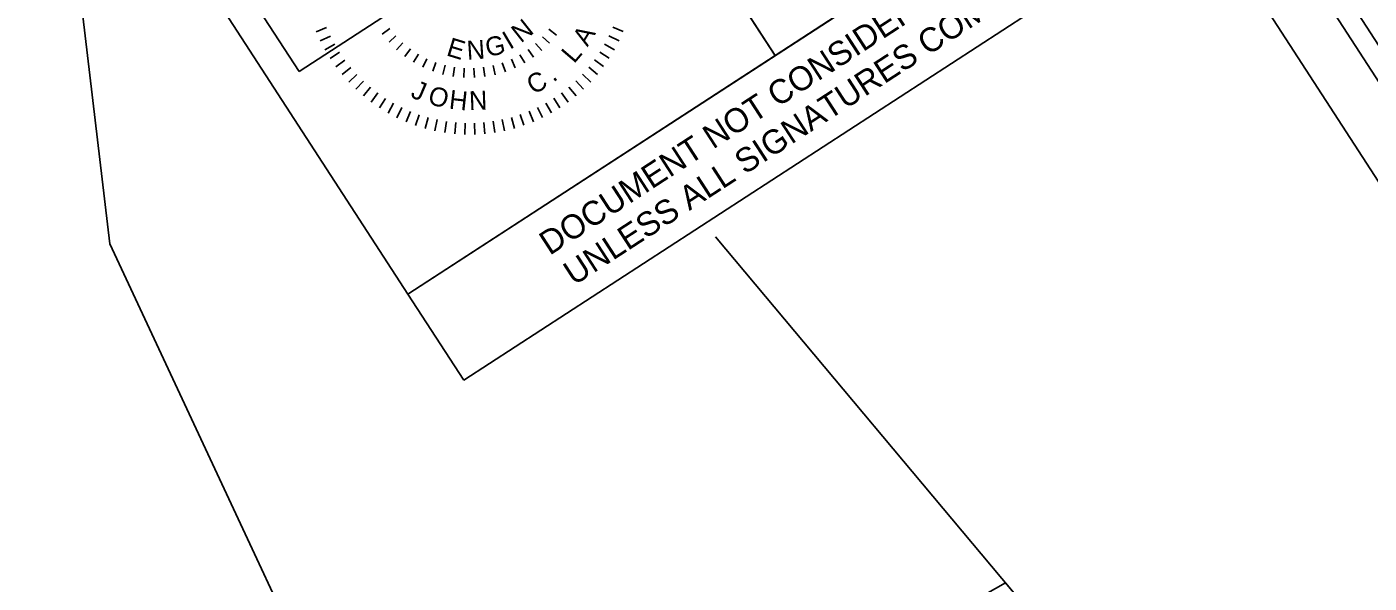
# Model space of a CAD drawing. Extents: x 555170 to 557181, y 503234 to 505074.
# Drawn here: x 556408.1 to 556715, y 504743 to 504870 of the extents above; entities that cross this region are included whole.
import ezdxf

# ---------------------------------------------------------------- set-up
doc = ezdxf.new("R2010")
doc.units = 0
for name, color, linetype in [('Matchline', 7, 'Continuous'), ('Old_Level_21', 7, 'Continuous'), ('Sheet Border Standard 30in CELL', 7, 'Continuous'), ('Sheet Clip Boundary CELL', 7, 'Continuous'), ('Sheet Plot Border Inside CELL', 7, 'Continuous'), ('Sheet Plot Border Outside CELL', 7, 'Continuous'), ('Sheet Sticker Exception Certification CELL', 7, 'Continuous'), ('Sheet Sticker Incomplete CELL', 7, 'Continuous')]:
    doc.layers.add(name, color=color, linetype=linetype)

msp = doc.modelspace()

# ---------------------------------------------------------------- linework, layer by layer
at = {"layer": 'Matchline'}
msp.add_line((556565.58, 504822.05), (556936.88, 504379.27), dxfattribs=at)
at = {"layer": 'Old_Level_21'}
for p, q in [((556474.26, 504868.87), (556476.65, 504869.86)), ((556475.2, 504866.78), (556477.53, 504867.91)), ((556489.37, 504868.33), (556491.09, 504869.63)), ((556490.93, 504866.48), (556492.51, 504867.94)), ((556527.6, 504866.28), (556526.02, 504867.76)), ((556529.17, 504868.12), (556527.46, 504869.44)), ((556543.52, 504866.82), (556541.19, 504867.95)), ((556544.46, 504868.91), (556542.07, 504869.9)), ((556476.27, 504864.75), (556478.52, 504866.02)), ((556477.46, 504862.78), (556479.63, 504864.19)), ((556492.65, 504864.77), (556494.09, 504866.38)), ((556494.53, 504863.25), (556495.8, 504864.99)), ((556523.96, 504863.09), (556522.7, 504864.84)), ((556525.85, 504864.6), (556524.43, 504866.22)), ((556541.27, 504862.82), (556539.1, 504864.23)), ((556542.46, 504864.78), (556540.2, 504866.06)), ((556478.77, 504860.89), (556480.85, 504862.43)), ((556496.54, 504861.92), (556497.64, 504863.77)), ((556498.67, 504860.78), (556499.6, 504862.73)), ((556500.91, 504859.85), (556501.64, 504861.88)), ((556503.23, 504859.15), (556503.76, 504861.24)), ((556505.6, 504858.67), (556505.92, 504860.81)), ((556512.84, 504858.63), (556512.54, 504860.77)), ((556515.22, 504859.08), (556514.71, 504861.19)), ((556516.82, 504861.8), (556517.52, 504859.76)), ((556519.78, 504860.66), (556518.88, 504862.62)), ((556521.93, 504861.78), (556520.84, 504863.64)), ((556538.56, 504859.12), (556536.56, 504860.78)), ((556539.97, 504860.93), (556537.88, 504862.46)), ((556480.18, 504859.09), (556482.17, 504860.74)), ((556481.7, 504857.37), (556483.59, 504859.14)), ((556508.01, 504858.43), (556508.12, 504860.58)), ((556510.43, 504858.41), (556510.33, 504860.57)), ((556537.03, 504857.4), (556535.15, 504859.18)), ((556483.33, 504855.75), (556485.1, 504857.63)), ((556485.05, 504854.22), (556486.71, 504856.22)), ((556486.85, 504852.81), (556488.39, 504854.9)), ((556531.89, 504852.84), (556530.36, 504854.93)), ((556533.69, 504854.26), (556532.04, 504856.25)), ((556535.41, 504855.78), (556533.64, 504857.66)), ((556488.75, 504851.51), (556490.15, 504853.68)), ((556490.71, 504850.32), (556491.98, 504852.58)), ((556492.74, 504849.26), (556493.87, 504851.59)), ((556526.01, 504849.28), (556524.87, 504851.61)), ((556528.04, 504850.35), (556526.76, 504852.6)), ((556530, 504851.54), (556528.59, 504853.71)), ((556494.84, 504848.32), (556495.82, 504850.71)), ((556496.98, 504847.51), (556497.82, 504849.95)), ((556499.17, 504846.82), (556499.87, 504849.32)), ((556501.4, 504846.28), (556501.94, 504848.81)), ((556517.35, 504846.29), (556516.81, 504848.82)), ((556519.58, 504846.83), (556518.88, 504849.33)), ((556521.77, 504847.52), (556520.92, 504849.97)), ((556523.92, 504848.34), (556522.92, 504850.73)), ((556503.66, 504845.86), (556504.05, 504848.42)), ((556505.94, 504845.59), (556506.17, 504848.17)), ((556508.23, 504845.45), (556508.31, 504848.04)), ((556510.52, 504845.45), (556510.45, 504848.04)), ((556512.82, 504845.59), (556512.58, 504848.17)), ((556515.09, 504845.87), (556514.7, 504848.43))]:
    msp.add_line(p, q, dxfattribs=at)
at = {"layer": 'Sheet Border Standard 30in CELL'}
msp.add_line((556517.88, 504957.83), (556579.13, 504863.53), dxfattribs=at)
for points in [[(556581.3, 505043.79), (555323.3, 504226.82), (555895.18, 503346.22), (557153.18, 504163.19)], [(556517.88, 504957.83), (556601.75, 505012.3), (556663.02, 504917.95), (556579.16, 504863.48)], [(556433.97, 504903.34), (556517.88, 504957.83), (556579.16, 504863.48), (556495.25, 504808.99)]]:
    msp.add_lwpolyline(points, close=True, dxfattribs=at)
at = {"layer": 'Sheet Clip Boundary CELL'}
msp.add_lwpolyline([(555838.52, 503433.47), (555757.63, 503602.94), (555641.38, 503854.94), (555665.07, 503867.43), (555636.39, 503915.75), (555617.07, 503908.99), (555456.45, 504257.61), (555437.06, 504299.18), (556413.52, 504934.83), (556427.07, 504820.42), (556498.53, 504667.56), (556631.84, 504743.04), (556936.88, 504379.27), (557153.18, 504163.19), (555896.02, 503346.77)], close=True, dxfattribs=at)
at = {"layer": 'Sheet Plot Border Inside CELL'}
msp.add_lwpolyline([(556590.39, 505052.74), (555192.76, 504145.08), (555767.42, 503260.21), (557165.05, 504167.86)], close=True, dxfattribs=at)
at = {"layer": 'Sheet Plot Border Outside CELL'}
msp.add_lwpolyline([(556581.94, 505074.02), (555169.63, 504156.83), (555768.74, 503234.3), (557181.05, 504151.49)], close=True, dxfattribs=at)
at = {"layer": 'Sheet Sticker Exception Certification CELL'}
for p, q in [((556495.25, 504808.99), (556663.01, 504917.94)), ((556675.81, 504898.23), (556508.05, 504789.28)), ((556508.05, 504789.28), (556495.25, 504808.99))]:
    msp.add_line(p, q, dxfattribs=at)
at = {"layer": 'Sheet Sticker Incomplete CELL'}
msp.add_lwpolyline([(556470.36, 504859.78), (556454.37, 504884.41), (556608.47, 504984.49), (556624.47, 504959.85)], close=True, dxfattribs=at)

# ---------------------------------------------------------------- texts
at = {"layer": 'Old_Level_21'}
for s, rotation, p in [('N', 38.3367, (556521.06, 504866.18)), ('E', 342.9909, (556503.82, 504863.53)), ('N', 3.846, (556508.82, 504862.48)), ('G', 12.6122, (556513.46, 504863.08)), ('I', 30.707, (556518.52, 504864.71)), ('A', 58.54, (556536.28, 504865.32)), ('L', 49.5374, (556533.22, 504861.46)), ('C', 29.0108, (556523.91, 504854.44)), ('.', 36.7531, (556528.47, 504857.25)), ('J', 336.8558, (556495.64, 504854.03)), ('O', 344.9277, (556499.57, 504852.49)), ('H', 353.5704, (556504.5, 504851.35)), ('N', 2.243, (556509.29, 504850.98))]:
    msp.add_text(s, height=4.31, rotation=rotation, dxfattribs=at).set_placement(p)
at = {"layer": 'Sheet Sticker Exception Certification CELL'}
for s, p in [('DOCUMENT NOT CONSIDERED FINAL', (556527.64, 504817.69)), ('UNLESS ALL SIGNATURES COMPLETED', (556533.17, 504810.79))]:
    msp.add_text(s, height=5.5, rotation=33.0007, dxfattribs=at).set_placement(p)

doc.saveas('drawing.dxf')
